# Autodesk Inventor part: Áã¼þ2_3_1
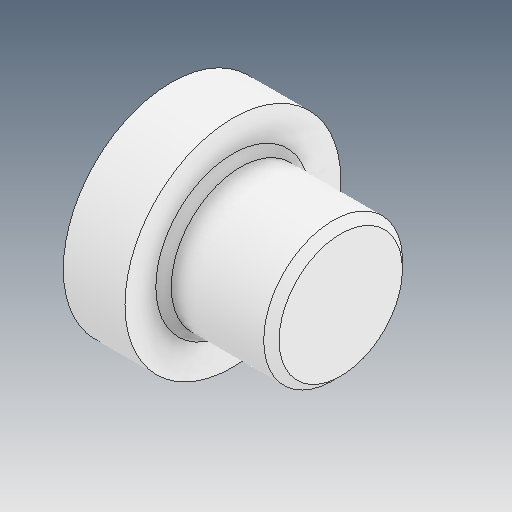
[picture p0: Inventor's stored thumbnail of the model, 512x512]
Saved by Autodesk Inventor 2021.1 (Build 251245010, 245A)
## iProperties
Created: 2021-05
Part Number: Áã¼þ2_3_1
Material: Ogólny
Document SubType Name: Modeling
Designer: user
Density: 1 g/cm^3
Appearance: Domyślna
Author: user
Revision Number: ÈÎºÎ
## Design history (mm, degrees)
feature "ÊäÈë1"
node "Bryła1"
